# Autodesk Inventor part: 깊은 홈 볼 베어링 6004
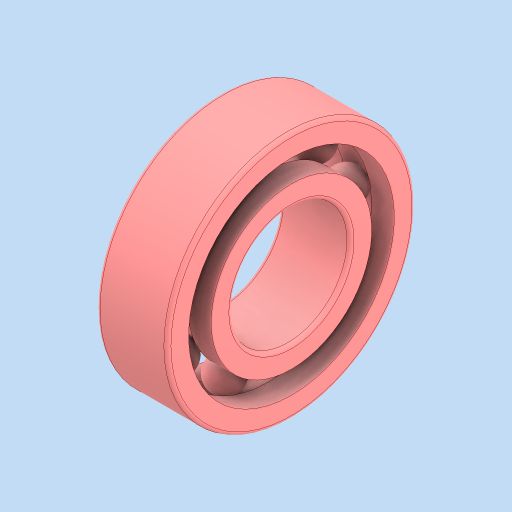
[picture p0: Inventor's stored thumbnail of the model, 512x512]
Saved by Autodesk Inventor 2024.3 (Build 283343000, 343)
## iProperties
Created: 2025-11
Part Number: 깊은 홈 볼 베어링 6004
Material: 강철, 연강
Description: 깊은 그루브 볼 베어링
Document SubType Name: Modeling
Designer: PC2-02
Density: 7.85 g/cm^3
Appearance: 기본값
Author: jhkim
Sending System: Autodesk Inventor 2026
Preprocessor: ST-DEVELOPER v20.1
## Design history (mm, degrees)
node "깊은 홈 볼 베어링 60041"
node "솔리드1"
node "솔리드2"
node "솔리드3"
node "솔리드4"
node "솔리드5"
node "솔리드6"
node "솔리드7"
node "솔리드8"
node "솔리드9"
node "솔리드10"
node "솔리드11"
body "Solid1"
node "Solid1:1"
node "Solid1:2"
node "Solid1:3"
node "Solid1:4"
node "Solid1:5"
node "Solid1:6"
node "Solid1:7"
node "Solid1:8"
node "Solid1:9"
node "Solid1:10"
